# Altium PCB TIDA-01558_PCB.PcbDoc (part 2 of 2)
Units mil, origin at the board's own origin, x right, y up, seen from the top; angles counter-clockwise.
Board outline 2362.2 x 2362.2 mil, 2 copper layers (Top Layer, Bottom Layer), stack 64.8 mil thick; 83 components, 39 nets, 200 pads, 58 vias.
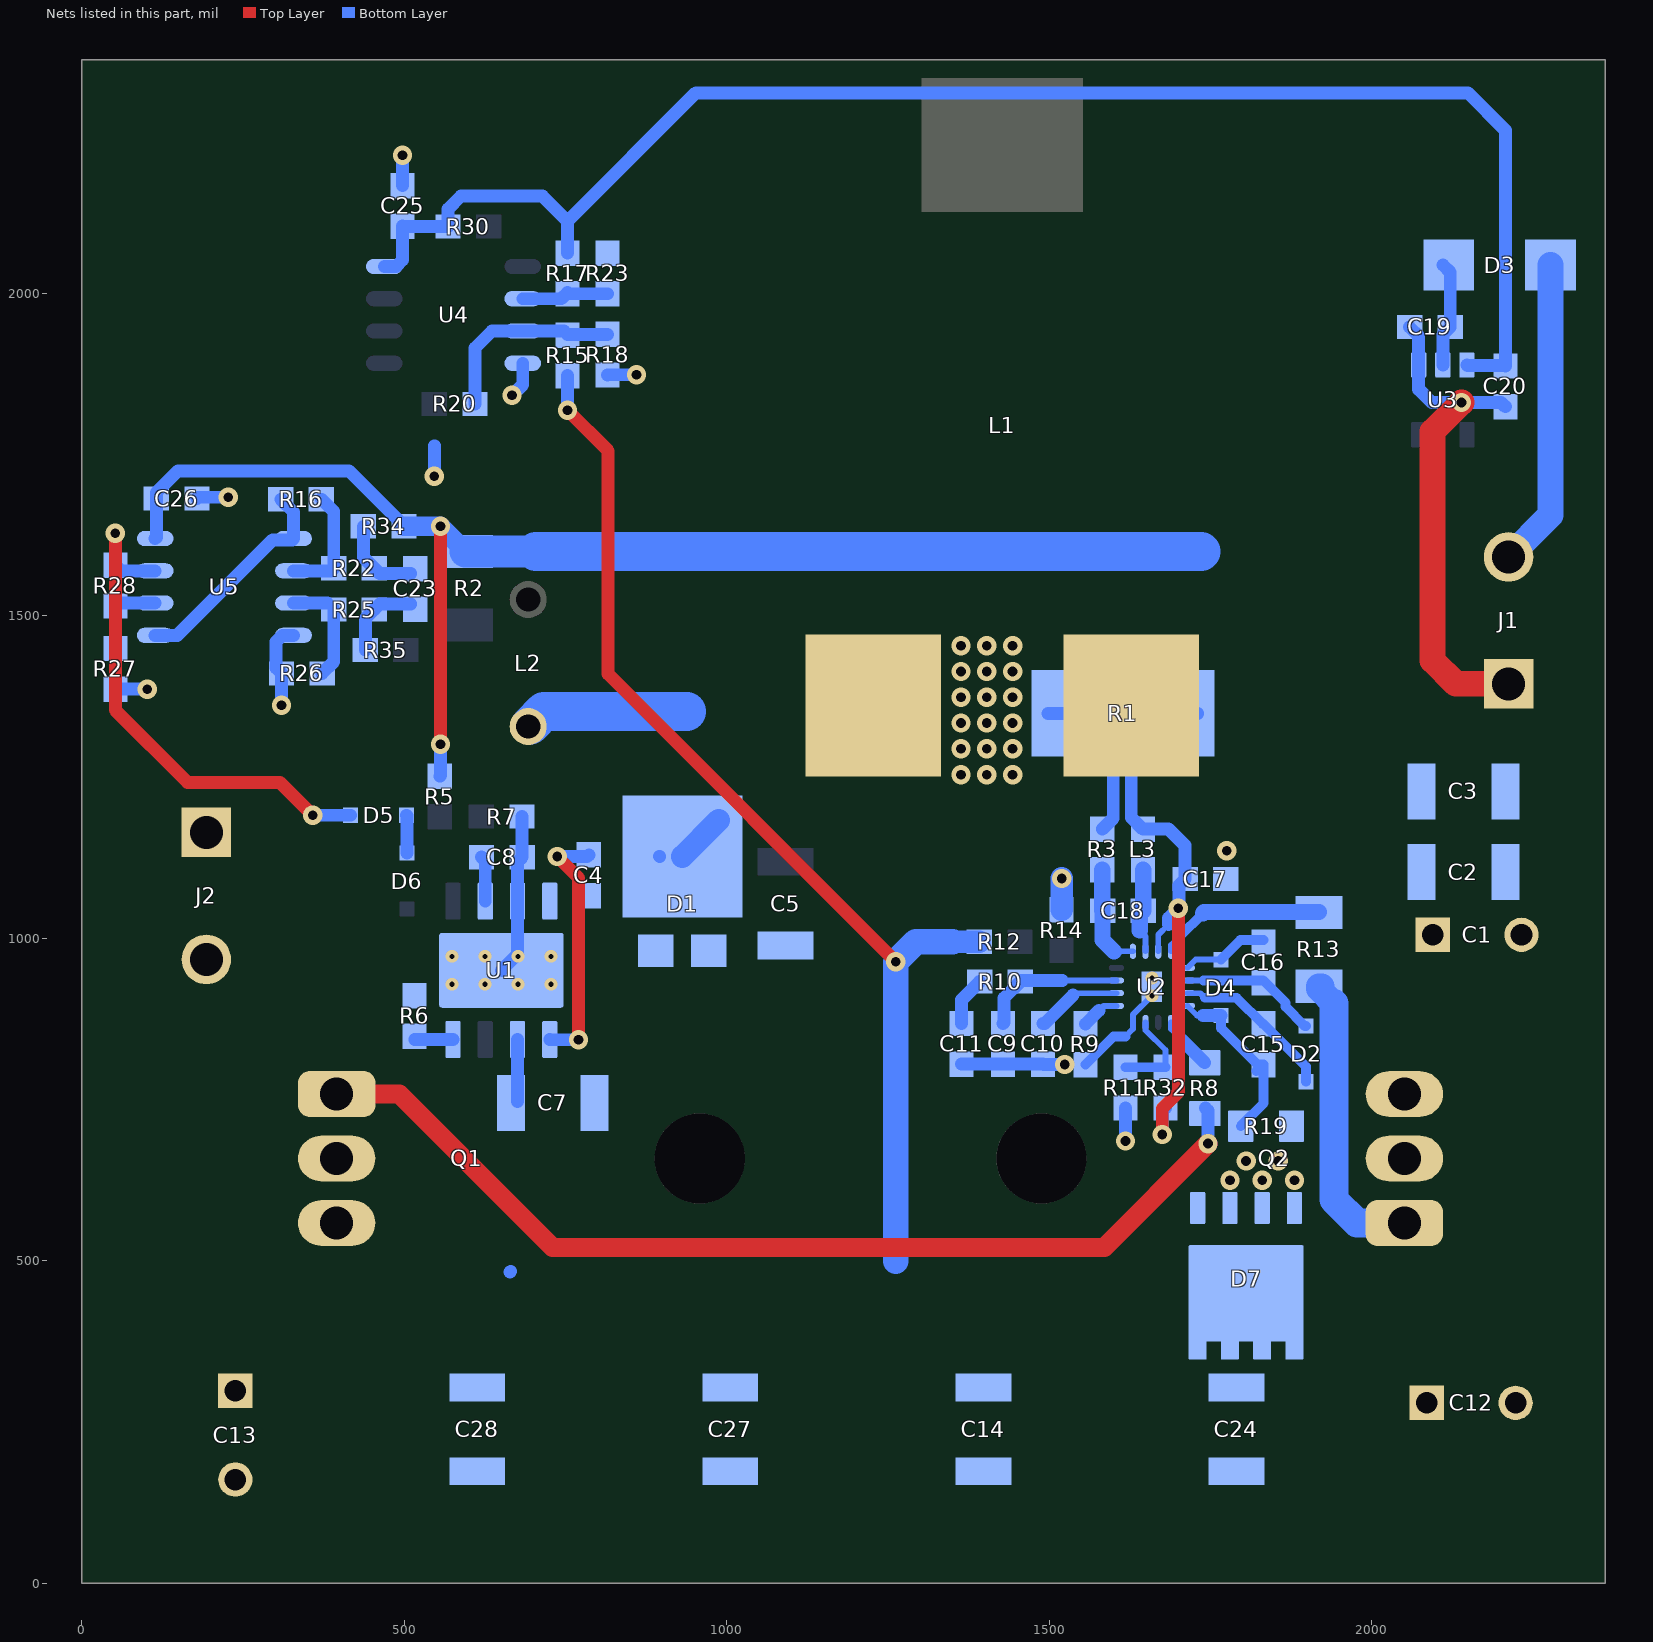
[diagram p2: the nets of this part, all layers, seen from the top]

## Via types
v1: diameter 30, hole 15, Top Layer to Bottom Layer, 48 vias
v2: diameter 19.68, hole 7.87, Top Layer to Bottom Layer, 10 vias

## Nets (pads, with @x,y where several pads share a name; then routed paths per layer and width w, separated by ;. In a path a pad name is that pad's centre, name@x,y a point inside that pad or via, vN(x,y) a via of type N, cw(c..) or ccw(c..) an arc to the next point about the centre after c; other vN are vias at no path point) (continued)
GND: C1.2 C2.2 C3.2 C5.2 C7.2 C8.2 C9.2 C10.2 C11.2 C12.2 C13.2 C14.2 C16.1 C17.2 C19.2 C20.2 C24.2 C25.2 C26.2 C27.2 C28.2 D1.1 D1.2 D4.2 J1.1 J2.1 Q2.3 R6.1 R7.1 R9.1 R11.1 R14.1 R18.1 R23.1 R26.1 R27.1 U1.7 U1.9@650.52,950.63 U2.9 U2.16 U2.17 U3.1 U4.4 U5.4 | length 2026.5
  Top Layer w40: v1(2139,1831) 2094,1786 2094,1431 2130,1395 J1.1@2203,1395
  Bottom Layer w9: 1618,848 1629.47,859.47 U2.16@1629.47,869.88 1629.47,881.69 v2(1659,911.22) ; U2.9@1714.12,954.53 1726.9,967.31 D4.2@1766,967.31
  Bottom Layer w15: R9.1@1556,804.5 1599.5,848 1618,848 ; D4.2@1766,967.31 1796.19,997.5 C16.1@1832,997.5
  Bottom Layer w20: R27.1@52,1386.5 v1(101.5,1386.5) ; C26.2@178.5,1682 180.5,1684 v1(227,1684) ; v1(309.5,1361.5) R26.1@309.5,1411 301,1419.5 301,1460 311,1470 U5.4@328.28,1470 ; C25.2@497.22,2167.27 v1(497.22,2214.22) ; v1(546.59,1716.41) 546.59,1763.82 ; U1.9@650.52,950.63 675.52,975.63 U1.7@675.52,1057.91 675.52,1118.83 C8.2@682.7,1126 R7.1@682.7,1188.8 ; v1(667,1842) 683.52,1858.52 U4.4@683.52,1891.86 ; R18.1@815,1873.5 815.5,1874 v1(860,1874) ; C11.2@1364,805.24 C9.2@1428,805.24 C10.2@1490,805.24 1490.73,804.5 v1(1524,804.5) ; v1(1618,686) R11.1@1618,737.24 ; C19.2@2058.5,1948 2072.6,1933.91 U3.1@2072.6,1889.13 2072.6,1851.4 2093,1831 v1(2139,1831) 2200.5,1831 C20.2@2207,1824.5
  Bottom Layer w35: R14.1@1519,1044.5 v1(1519,1093)
  other v1: 1775,1136
  other v2: 573.75,928.97 624.93,928.97 676.11,928.97 727.29,928.97 1659,938.78 573.75,972.28 624.93,972.28 676.11,972.28 727.29,972.28
ISNS+: C18.1 L3.1 U2.6 | length 132.6
  Bottom Layer w9: 1640.09,1012.09 1649.16,1003.01 U2.6@1649.16,980.12
  Bottom Layer w25: 1640.09,1012.09 1640.09,1037.59 C18.1@1645.5,1043 1645.5,1106.01 L3.1@1645,1106.5
ISNS-: C18.2 R3.1 U2.5 | length 163.5
  Bottom Layer w9: 1600,980 1600.12,980.12 U2.5@1629.47,980.12
  Bottom Layer w25: R3.1@1582,1106.5 1582,1043.5 C18.2@1582.5,1043 1582.5,997.5 1600,980
LDO_OP: C20.1 C25.1 R17.2 R30.1 U3.3 U4.8 | length 2428.1
  Bottom Layer w20: U4.8@468.95,2041.86 487.31,2041.86 497.22,2051.77 C25.1@497.22,2104.28 497.72,2103.77 R30.1@567.72,2103.77 567.72,2130.72 588,2151 714,2151 753,2112 ; R17.2@753,2062.5 753,2112 ; U3.3@2147.4,1889.13 2148.04,1888.5 2206,1888.5 C20.1@2207,1887.5 2207,2253 2149,2311 952,2311 753,2112
NetC4_1: C4.1 U1.1 | length 392.6
  Top Layer w20: v1(737,1127) 770,1094 v1(770,843)
  Bottom Layer w20: U1.1@725.68,843.5 U1.1@725.52,843.34 725.87,843 v1(770,843) ; v1(737,1127) 783.5,1127 C4.1@786,1129.5
NetC4_2: C4.2 D1.3 L2.1 U1.8 | length 332.3
  Bottom Layer w20: D1.3@895.43,1127.48 D1.3@895.93,1126.97
  Bottom Layer w35: D1.3@931,1127.11 D1.3@987.38,1183.5
  Bottom Layer w60: L2.1@695,1330.57 716.43,1352 938,1352
NetC8_1: C8.1 U1.6 | length 70.5
  Bottom Layer w20: C8.1@619.7,1126 625.52,1120.18 U1.6@625.52,1057.91
NetC9_1: C9.1 R10.2 U2.3 | length 225.6
  Bottom Layer w9: 1520,934.84 U2.3@1603.88,934.84
  Bottom Layer w20: C9.1@1428,868.23 1429.57,869.8 1429.57,907.57 R10.2@1455,933 1456.84,934.84 1520,934.84
NetC11_1: C11.1 R10.1 | length 76.4
  Bottom Layer w20: C11.1@1364,868.23 1364,904.99 R10.1@1392.01,933
NetC15_1: C15.1 D4.1 R19.1 U2.12 | length 290.4
  Bottom Layer w9: U2.12@1714.12,895.47 1728.9,880.69 1738.31,880.69
  Bottom Layer w15: D4.1@1766,880.69 D4.1@1766,880.39 1766,861 1822.5,804.5 1831,804.5 C15.1@1821,794.5 ; R19.1@1796.63,709 1831.93,744.3 C15.1@1831.93,804.5
  Bottom Layer w20: 1738.31,880.69 D4.1@1766,880.69
NetC15_2: C15.2 D2.1 U2.11 | length 253.8
  Bottom Layer w9: U2.11@1714.12,915.16 1714.31,914.97 1734,914.97 1740.97,908
  Bottom Layer w15: 1740.97,908 1790.5,908 C15.2@1831,867.5 ; C15.2@1831.93,867.5 1898,801.43 D2.1@1898,777.69
NetC16_2: C16.2 D2.2 U2.10 | length 216.8
  Bottom Layer w9: U2.10@1714.12,934.84 1739,934.84
  Bottom Layer w15: 1739,934.84 1831.66,934.84 1866.01,900.5 1866.01,894.15 1895.86,864.31 D2.2@1898,864.31
NetC19_1: C19.1 D3.2 U3.2 | length 164.3
  Bottom Layer w20: U3.2@2110,1889.13 2110,1936.5 C19.1@2121.5,1948 2121.5,2032.76 D3.2@2110.26,2044
NetC23_1: C23.1 R22.1 R34.2 | length 132
  Bottom Layer w20: R34.2@436.5,1639 436.5,1590.99 R22.1@453.5,1574 461.87,1565.62 C23.1@510,1565.62
NetC23_2: C23.2 R25.1 R35.2 | length 128.8
  Bottom Layer w20: R35.2@439.5,1447 439.5,1496.01 R25.1@453.5,1510 461.87,1518.38 C23.2@510,1518.38
NetD5_1: D5.1 R28.1 U5.7 | length 820.9
  Top Layer w20: v1(52,1628) 52,1354 164,1242 307,1242 v1(358,1191)
  Bottom Layer w20: v1(52,1628) R28.1@52,1578.5 60.5,1570 U5.7@113.72,1570 ; v1(358,1191) D5.1@416.69,1191
NetD5_2: D5.2 D6.2 | length 59
  Bottom Layer w20: D5.2@503.31,1191 504,1190.31 D6.2@504,1132.31
NetD7_1: D7.1 D7.2 D7.3 D7.4 L1.2 Q1.3 Q2.2@2050.39,658.89 R19.2 | length 68.7
  Top Layer w60: L1.2@1626.8,1360.84 L1.2@1626.8,1380.2
  Top Layer w80: L1.2@1626.8,1360.84 L1.2@1676.16,1360.84
  other v1: 1780,625 1830,625 1880,625 1805,655 1855,655
NetL1_1: L1.1 R1.2 R3.2 | length 269.5
  Bottom Layer w20: R1.2@1497.86,1349 1568,1349 1599,1318 1599,1186.5 R3.2@1582,1169.5
  other v1: 1363,1254 1403,1254 1443,1254 1363,1294 1403,1294 1443,1294 1363,1334 1403,1334 1443,1334 1363,1374 1403,1374 1443,1374 1363,1414 1403,1414 1443,1414 1363,1454 1403,1454 1443,1454
NetQ1_1: Q1.1 R8.2 | length 1572.9
  Top Layer w30: Q1.1@395.17,758.88 492.12,758.88 730,521 1585,521 v1(1746,682)
  Bottom Layer w20: R8.2@1742,737.24 1746,733.24 v1(1746,682)
NetQ2_1: Q2.1 R13.2 | length 492.8
  Bottom Layer w30: Q2.1@2033.51,542 Q2.1@2050.39,558.89
  Bottom Layer w40: R13.2@1922.09,925.91 R13.2@1918,925.91 1918,922 1941,899
  Bottom Layer w45: 1941,899 1941,595 1977.11,558.89 Q2.1@2050.39,558.89
NetR6_2: R6.2 U1.4 | length 59.4
  Bottom Layer w20: R6.2@516.2,843.5 516.36,843.34 U1.4@575.52,843.34
NetR8_1: R8.1 U2.13 | length 84.2
  Bottom Layer w9: U2.13@1688.53,869.88 1688.53,859.84 1705.37,843
  Bottom Layer w20: 1705.37,843 R8.1@1741,807.37
NetR9_2: R9.2 U2.1 | length 59.5
  Bottom Layer w9: 1576.75,888.25 1583.98,895.47 U2.1@1603.88,895.47
  Bottom Layer w20: R9.2@1556,867.5 1576.75,888.25
NetR11_2: R11.2 R32.2 U2.15 | length 144.4
  Bottom Layer w9: U2.15@1649.16,869.88 1649.16,857.84 1680,827 R32.2@1680,800.23
  Bottom Layer w15: R11.2@1618,800.23 R32.2@1680,800.23
NetR13_1: R13.1 U2.8 | length 260.3
  Bottom Layer w9: U2.8@1688.53,980.12 1688.53,989.64 1701.71,1002.83
  Bottom Layer w15: 1701.71,1002.83 1737.96,1039.07
  Bottom Layer w25: 1738,1039.07 1740.01,1041.09 R13.1@1918,1041.09
NetR15_1: R15.1 R18.2 R20.1 U4.3 | length 305.3
  Bottom Layer w20: R20.1@609.58,1828.82 609.58,1915.58 635.86,1941.86 U4.3@683.52,1941.86 747.59,1941.86 752.99,1936.46 R18.2@815,1936.5 R18.2@815,1936.5
NetR16_1: R16.1 R22.2 U5.2 | length 178.8
  Bottom Layer w20: U5.2@328.28,1570 386.5,1570 R22.2@390.5,1574 390.5,1661.99 R16.1@371.5,1681
NetR16_2: R16.2 U5.1 U5.5 | length 343.1
  Bottom Layer w20: U5.5@113.72,1470 148,1470 296,1618 U5.1@326.28,1618 ; R16.2@308.5,1681 328.28,1661.22 U5.1@328.28,1620
NetR17_1: R17.1 R23.2 U4.2 | length 135.5
  Bottom Layer w20: U4.2@683.52,1991.86 743.35,1991.86 R17.1@753,2001.5 ; R17.1@753,1999.5 R23.2@815.07,1999.5
NetR25_2: R25.2 R26.2 U5.3 | length 158.7
  Bottom Layer w20: U5.3@328.28,1520 R25.2@380.5,1520 ; R26.2@372.5,1411 390.5,1429.01 R25.2@390.5,1510
NetR27_2: R27.2 R28.2 U5.6 | length 129.6
  Bottom Layer w20: R27.2@52,1449.5 R28.2@52,1515.5 56.5,1520 U5.6@113.72,1520
SS: C10.1 U2.2 | length 134.1
  Bottom Layer w9: 1535.52,913.75 1536.93,915.16 U2.2@1603.88,915.16
  Bottom Layer w20: C10.1@1490,868.23 1492.81,868.23 1536.93,912.35
VBAT: C1.1 C2.1 C3.1 C17.1 C26.1 D3.1 J1.2 L3.2 R1.1 R2.2 R5.2 R32.1 R34.1 U2.7 U5.8 | length 3557.2
  Top Layer w20: v1(556,1301) v1(556,1639) ; v1(1675,696) 1675,736.54 1700,761.54 v1(1700,1047)
  Bottom Layer w9: U2.7@1668.84,980.12 1668.84,1005.84 1684.84,1021.84
  Bottom Layer w20: U5.8@113.72,1620 115.5,1621.79 C26.1@115.5,1682 115.5,1691.5 149,1725 414.17,1725 499.5,1639.67 R34.1@499.5,1639 ; R5.2@555,1251.5 556,1252.5 v1(556,1301) ; v1(1675,696) 1675,732.24 R32.1@1680,737.24 ; 1684.84,1021.84 1684.84,1031.84 v1(1700,1047) 1701,1048 1701,1082.5 C17.1@1710.5,1092 1710,1092.5 1710,1144.5 1685.01,1169.5 L3.2@1645,1169.5 1627,1187.5 1627,1315 1661,1349 R1.1@1730.14,1349
  Bottom Layer w30: R34.1@499.5,1639 v1(556,1639) R2.2@594.91,1600.09
  Bottom Layer w40: J1.2@2212,1591.43 2276.74,1656.17 D3.1@2276.74,2044
  Bottom Layer w50: R2.2@594.91,1600.09 R2.2@601,1600.09 704.09,1600.09
  Bottom Layer w60: 704.09,1600.09 1735.09,1600.09
VLINE: C7.1 C12.1 C13.1 C14.1 C24.1 C27.1 C28.1 D7.5 D7.6 D7.7 D7.8 D7.9 J2.2 Q1.2@395.17,658.88 R12.2 R15.2 U1.2 | length 1823
  Top Layer w20: v1(753,1819) 816,1756 816,1410 v1(1262,964)
  Bottom Layer w20: 664,483 665.04,484.04 ; C7.1@675.52,747.52 U1.2@675.52,843.34 ; v1(753,1819) R15.2@753,1872.5
  Bottom Layer w35: 1350,995 R12.2@1391.5,995
  Bottom Layer w40: 1262,500 v1(1262,964) 1293,995 1350,995
pads on no net: H13. L1.3 Q1.2@798.02,658.88 Q2.2@1647.55,658.89 U1.9@650.52,950.63 U2.14 U3.4 U3.5 U4.5 U4.6 U4.7

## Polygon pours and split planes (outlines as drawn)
GND on Bottom Layer "GND_L02_P043" (solid, remove dead copper, pour order 43): 0,1388 52,1336 482,1336 538,1392 538,1503 876,1841 876,2268 781,2363 34,2363 0,2329
GND on Bottom Layer "GND_L02_P041" (solid, remove dead copper, pour order 41): 42,1296 209,1296 496,1009 622,1009 622,883 472,883 309,1046 174,1046 137,1009 137,313.37 220.37,230 2126,230 2144,248 2144,310 1974,480 1974,932 1994,952 2124,952 2137,965 2137,1425 2192,1480 2303,1480 2362.2,1420.8 2362.2,53.2 2309,0 70,0 2,68 2,1256
VBAT on Bottom Layer "VBAT_L02_P008" (solid, remove dead copper, pour order 8): 1700,1404 1700,1274 1754,1220 1825,1220 2072,973 2117,973 2122,978 2122,1447 2253,1578 2253,1635 2201,1687 1761,1687 1701.23,1627.23
NetL1_1 on Bottom Layer "NETL1_1_L02_P010" (solid, remove dead copper, pour order 10): 1502,1484 1526,1460 1526,1268 1497,1239 1175,1239 1150,1264 1150,1453 1181,1484
GND on Bottom Layer "GND_L02_P012" (solid, remove dead copper, pour order 12): 1136,1012 1146,1002 1146,855 980.88,689.88 784.12,689.88 762,712 762,879 753,888 496,888 488,896 488,1005 495,1012
NetC4_2 on Bottom Layer "NETC4_2_L02_P014" (solid, remove dead copper, pour order 14): 1023.61,1027.5 1025.49,1029.38 1025.49,1383 828,1383 828,1107 811,1090 715,1090 710,1085 710,1034 716.5,1027.5
VLINE on Bottom Layer "VLINE_L02_P049" (solid, remove dead copper, pour order 49): 153,998 153,319 226,246 2106,246 2114,254 2114,309 1885,538 902,538 612,828 504,828 316,1016 171,1016
NetD7_1 on Bottom Layer "Bottom Layer-No Net" (solid, remove dead copper, pour order 55): 1852,685 1841,674 1781,674 1716,609 1716,560 1720,556 1894.92,556 1900,561.08 1900,733 1896,737 1855,737 1852,734
GND on Bottom Layer "GND_L02_P057" (solid, remove dead copper, pour order 57): 1292,762 1435,619 1828,619 2083,874 2083,940 1818,1205 1342,1205 1292,1155
GND on Top Layer "NET" (solid, remove dead copper, pour order 53): 1291,1150 1291,743.74 1352.74,682 1382.74,652 1724,652 1746,652 1792,698 1792,1165 1752,1205 1343,1205 1292,1154
GND on Top Layer "GND_L01_P045" (solid, remove dead copper, pour order 45): 4,2270 4,85 68.61,20.39 2313.39,20.39 2355,62 2355,1426 2323,1458 2073,1458 1988,1373 1988,564 1652,228 418,228 299,347 299,831 335,867 411,867 497,867 612,752 632,732 819,732 839,752 839,1188 812,1215 659,1215 594,1280 594,1558 875.82,1839.82 875.82,2266.18 784,2358 87,2358 1,2272
NetD7_1 on Top Layer "NETD7_1_L01_P027" (solid, remove dead copper, pour order 27): 332,575 332,350 437,245 1627,245 2003,621 2093,621 2113,641 2113,677 2093,697 2011.74,697 1971,737.74 1971,914 1971,1363 1860,1474 1523,1474 1518,1469 1518,1253 1525,1246 1751,1246 1812,1185 1812,698 1615,501 632,501 535,598 355,598
NetL1_1 on Top Layer "NETL1_1_L01_P015" (solid, remove dead copper, pour order 15): 1111,1467 1111,1258 1137,1232 1450,1232 1466,1248 1466,1458 1442,1482 1126,1482

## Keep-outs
Keep-Out Layer:
  the board outline again, w10

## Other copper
Top Layer:
  text ".Layer_Name" at 271,-1248.49 h60
Bottom Layer:
  text ".Layer_Name" at 271,-1248.49 h60

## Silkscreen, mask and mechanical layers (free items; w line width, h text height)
Top Overlay:
  lines w10: 2266,1296 2266,1287 ; 2303,1286 2303,1278 2266,1278 2266,1287 ; 2304,1296 2303,1295 2303,1287 2266,1287
  text "TIDA-01558-E1" at 44,2001 h120
  text "20-28V,20A" at 2047,1777 h30
  text "VBAT" at 2141,1712 h40
  text "GND" at 145,1282 h40
  text "GND" at 2129,1238 h40
  text "VLINE" at 29,815 h40
  text "30-38V,20A" at 65,499 h30 r90
  text ".Layer_Name" at 271,-1248.49 h60
Bottom Overlay:
  lines w6: 419,1410 419,1401 424,1396 624,1396 657,1429 657,1654 622,1689 427,1689 419,1681 419,1675 ; 869,1791 869,1801 874,1806 968,1806 1008,1766 1008,1617 976,1585 878,1585 870,1593 870,1598 ; 1353,758 1392,758 1400,766 ; 1439,741 1457,741 1481,765 ; 1540,1113 1540,1087 1546,1081 ; 1587,685 1587,692 1590,695 ; 1647,680 1647,692 1652,697 ; 1716,685 1716,693 1720,697 ; 1942,873 1986,873 1993,866
  text ".Layer_Name" at 271,-1248.49 h60
Top Paste:
  text ".Layer_Name" at 271,-1248.49 h60
Bottom Paste:
  text ".Layer_Name" at 271,-1248.49 h60
Top Solder:
  text ".Layer_Name" at 271,-1248.49 h60
  text ".Layer_Name" at 271,-1248.49 h60
Bottom Solder:
  text ".Layer_Name" at 271,-1248.49 h60
Drill Guide:
  text ".Layer_Name" at 271,-1248.49 h60
M1 Board Outline:
  the board outline again, w10
M2 Board Dimensions:
  rectangle: -306,-665 -181,-540
  rectangle: -181,-790 194,-665
  lines w7: -306,-665 694,-665 ; -181,-790 -181,-540 ; -56,-790 -56,-540 ; 194,-790 194,-540 ; 444,-790 444,-540 ; -306,-790 694,-790 694,-540 -306,-540 -306,-790
M3 3D STEP Top:
  text ".Layer_Name" at 271,-1248.49 h60
M4 3D STEP Bottom:
  text ".Layer_Name" at 271,-1248.49 h60
M5 Assembly Top:
  lines w10: -598,-1320.17 6002,-1320.17 ; -598,-1116.83 6004,-1116.83 ; -598,-913.5 -598,-1523.5 3407,-1523.5 6004,-1523.5 6004,-913.5 -597.5,-913.5 -597.5,-1523.5 978,-1523.5 ; 1867,-1523.5 1867,-913.5 ; 3134,-1116.83 3134,-913.5 ; 3974,-1116.83 3974,-913.5 ; 4596,-1530 4596,-1327.17
  text "COMPONENTS MARKED 'DNP' SHOULD NOT BE POPULATED." at 847.5,-708.5 h60
  text "ASSEMBLY VARIANT:" at 847,-824 h60
  text ".VariantName" at 1883,-824 h60
  text "PCB VIEWED FROM TOP SIDE" at -534.5,-1045.67 h60
  text "BOARD #:" at 1942,-1045.67 h60
  text ".PRJ_Number" at 2487.5,-1045.67 h60
  text "REV:" at 3332,-1045.67 h60
  text ".PCB_Rev" at 3623.5,-1045.67 h60
  text "SVN REV:" at 4170,-1045.67 h60
  text ".VersionControl_RevNumber" at 4676,-1045.67 h60
  text "LAYER NAME =" at -534.5,-1248.49 h60
  text "'.Layer_Name'" at 271,-1248.49 h60
  text "TID #:" at 1942,-1249 h60
  text ".TID" at 2487.5,-1249 h60
  text "PLOT NAME =" at -534.5,-1454.34 h60
  text ".plot_File_Name" at 271,-1454.34 h60
  text "GENERATED    :" at 1944,-1454.34 h60
  text ".Print_Date" at 2813.5,-1454.34 h60
  text ".Print_Time" at 3542.5,-1454.34 h60
  text "TEXAS INSTRUMENTS" at 4807,-1454.34 h60
M6 Assembly Bottom:
  circle w10: c2048.98,1881 r1
  lines w10: -598.5,-1117.33 6003.5,-1117.33 ; -596.5,-1320.67 6003.5,-1320.67 ; 809.5,-1530.5 809.5,-1327.67 ; 1431.5,-1117.33 1431.5,-914 ; 2271.5,-1117.33 2271.5,-914 ; 3538.5,-1524 3538.5,-914 ; 4427.5,-1524 6003,-1524 6003,-914 -598.5,-914 -598.5,-1524 1998.5,-1524 6003.5,-1524 6003.5,-914
  text "COMPONENTS MARKED 'DNP' SHOULD NOT BE POPULATED." at 5796,-708 h60
  text ".VariantName" at 4752,-824 h60
  text "ASSEMBLY VARIANT:" at 5791,-824 h60
  text ".VersionControl_RevNumber" at 729.5,-1046.17 h60
  text "SVN REV:" at 1235.5,-1046.17 h60
  text ".PCB_Rev" at 1782,-1046.17 h60
  text "REV:" at 2073.5,-1046.17 h60
  text ".PRJ_Number" at 2918,-1046.17 h60
  text "BOARD #:" at 3463.5,-1046.17 h60
  text "PCB VIEWED FROM BOTTOM SIDE" at 5940,-1046.17 h60
  text "LAYER NAME =" at 5937,-1243 h60
  text "'.Layer_Name'" at 5184,-1244 h60
  text ".TID" at 2918,-1249.5 h60
  text "TID #:" at 3463.5,-1249.5 h60
  text "TEXAS INSTRUMENTS" at 598.5,-1454.84 h60
  text ".Print_Time" at 1863,-1454.84 h60
  text ".Print_Date" at 2592,-1454.84 h60
  text "GENERATED    :" at 3461.5,-1454.84 h60
  text ".plot_File_Name" at 5134.5,-1454.84 h60
  text "PLOT NAME =" at 5940,-1454.84 h60
M9 Title Sheet:
  drawing of 57 lines, arcs and shapes, not listed
  text "1" at 433.84,7646.5 h70
  text "2" at 2929.5,7646.5 h70
  text "3" at 5418.84,7646.5 h70
  text "4" at 7925.51,7646.5 h70
  text "5" at 10424.5,7646.5 h70
  text "6" at 12929.5,7646.5 h70
  text "A" at -722.5,6503.5 h70
  text "A" at 14077.5,6503.5 h70
  text "B" at -722.5,4123.5 h70
  text "B" at 14077.5,4123.5 h70
  text "C" at -722.5,1748.5 h70
  text "C" at 14077.5,1748.5 h70
  text "PROJECT TITLE:" at 11037.5,-112.5 h45
  text ".PRJ_Title" at 11087.5,-245.83 h70
  text "DESIGNED FOR:" at 11037.5,-413.5 h45
  text ".PRJ_Customer" at 11087.5,-553.5 h70
  text "D" at -722.5,-621.5 h70
  text "D" at 14077.5,-621.5 h70
  text "FILE NAME:" at 11037.5,-713.5 h45
  text ".PCB_File_Name_No_Path" at 11087.5,-833.5 h70
  text "Texas Instruments (TI) and/or its licensors do not warrant the accuracy or completeness of this specification" at 6068,-995.34 h45
  text "ENGINEER:" at 11037.5,-1003.5 h45
  text "LAYOUT BY:" at 12542.5,-1003.5 h45
  text "or any information contained therein. TI and/or its licensors do not warrant that this design will meet" at 6023.01,-1108 h45
  text ".PRJ_Engineer" at 11087.5,-1158.49 h70
  text ".PCB_Layout" at 12593,-1158.49 h70
  text "the specifications, will be suitable for your application or fit for any particular purpose, or will operate in" at 6023.01,-1220.67 h45
  text "ALTIUM DESIGNER VERSION:" at 12542.5,-1313.5 h45
  text "an implementation. TI and/or its licensors do not warrant that the design is production worthy. You should" at 6023.01,-1333.33 h45
  text "completely validate and test your design implementation to confirm the system functionality for your application." at 6068,-1446 h45
  text ".print_Scale" at 11087.5,-1446.83 h70
  text ".Application_BuildNumber" at 12593,-1446.83 h70
  text "1" at 433.84,-1653.5 h70
  text "2" at 2929.5,-1653.5 h70
  text "3" at 5418.84,-1653.5 h70
  text "4" at 7925.51,-1653.5 h70
  text "5" at 10424.5,-1653.5 h70
  text "6" at 12929.5,-1653.5 h70
M10 Fab Notes:
  drawing of 173 lines, arcs and shapes, not listed
  text "DESIGN INFORMATION" at 12071.02,5811 h60
  text "MIN. TRACK WIDTH:" at 11426.46,5631 h60
  text "9" at 12522.7,5631 h60
  text "MIL" at 12677.46,5631 h60
  text "MIN. CLEARANCE:" at 11426.46,5499 h60
  text "0.2" at 12462.7,5499 h60
  text "mm" at 12677.46,5499 h60
  text "19.68" at 12374,5370 h60
  text "MIN. VIA PAD SIZE:" at 11426.46,5367 h60
  text "MIL" at 12677.46,5367 h60
  text "0.05mm (2MIL)" at 12121.46,5225.29 h60
  text "MINIMUM ANNULAR RING" at 11097.23,5221 h60
  text "EXTERNAL" at 12829.46,5221 h60
  text "PER" at 11297.23,5103 h60
  text "IPC-D-275 CLASS 2 LEVEL C" at 11517.23,5103 h60
  text "MIL, HOLES" at 13005.46,4990.71 h60
  text "+/-" at 12613,4990 h60
  text "+/-" at 13467,4990 h60
  text "REGISTRATION TOLERANCES:" at 11097.23,4985 h60
  text "METAL" at 12297,4985 h60
  text "5" at 12873.2,4985 h60
  text "3" at 13706.2,4985 h60
  text "MIL" at 13822.46,4985 h60
  text "+/-" at 13467,4872 h60
  text "HOLE SIZE TOLERANCE (UNLESS OTHERWISE SPECIFIED):" at 11097.23,4867 h60
  text "3" at 13706.2,4867 h60
  text "MIL" at 13822.46,4867 h60
  text "MATERIAL:" at 11022.46,4657.54 h60
  text "FR-4 High Tg" at 12008.9,4517.21 h60
  text "FR-408" at 11443.46,4508.64 h60
  text "OTHER" at 12931.46,4508.64 h60
  text "X" at 11854,4505 h60
  text "62 MIL (1.6mm) +/-10%" at 11763.56,4345.92 h60
  text "THICKNESS:" at 11097.23,4341.64 h60
  text "X" at 11635.4,4341.64 h60
  text "OTHER" at 13048.46,4341.64 h60
  text "TOLERANCE:" at 11097.23,4183.64 h60
  text "X" at 11936.53,4183.64 h60
  text "ANSI IPC-6012 TYPE 3 CLASS 2" at 12123.48,4183.64 h60
  text "OTHER +/-" at 12123.46,4027.64 h60
  text "BOW & TWIST:" at 11097.23,3870.64 h60
  text "X" at 11936.53,3870.64 h60
  text "ANSI IPC-6012 TYPE 3 CLASS 2" at 12123.48,3870.64 h60
  text "OTHER +/-" at 12123.46,3712.13 h60
  text "DRILLING:" at 11022.46,3573.64 h60
  text "REFERENCE:" at 11097.23,3456.64 h60
  text "X" at 11745.46,3456.64 h60
  text "AS SHOWN" at 11932.46,3456.64 h60
  text "X" at 12646.46,3456.64 h60
  text "NC_DRILL FILES" at 12783.46,3456.64 h60
  text "PTH COPPER THICKNESS:" at 11097.23,3298.64 h60
  text "X" at 12227.46,3298.64 h60
  text "20-30 um" at 12364.46,3298.64 h60
  text "OTHER" at 13081.46,3298.64 h60
  text "BOARD FINISH:" at 11022.46,3139.64 h60
  text "SILKSCREEN:" at 11177.68,3021.64 h60
  text "X" at 12126.46,3021.64 h60
  text "TOP" at 12252.46,3021.64 h60
  text "X" at 12636.46,3021.64 h60
  text "BOTTOM" at 12763.46,3021.64 h60
  text "SILKSCREEN COLOR:" at 11177.68,2854.64 h60
  text "X" at 12125.42,2854.64 h60
  text "WHITE" at 12252.46,2854.64 h60
  text "OTHER" at 12763.46,2854.64 h60
  text "X" at 12256.42,2695.44 h60
  text "GREEN" at 12383.46,2695.44 h60
  text "OTHER" at 13001.46,2695.44 h60
  text "SOLDER RESIST COLOR:" at 11177.68,2684.64 h60
  text "X" at 12256.42,2525.44 h60
  text "MATTE" at 12383.46,2525.44 h60
  text "SEMI-GLOSS" at 13001,2524.8 h60
  text "IMMERSION GOLD (ENIG)" at 12083.46,2336.92 h60
  text "ENEPIG" at 13421,2333.64 h60
  text "SURFACE FINISH:" at 11022.46,2332.64 h60
  text "X" at 11896.51,2332.64 h60
  text "IMM. TIN/SILVER OR EQUIV" at 11352,2175.64 h60
  text "OTHER" at 12783.46,2175.64 h60
  text "ARRAY/PANEL:" at 11022.46,1996.64 h60
  text "CUT AND TRIM PER M1 BOARD OUTLINE" at 12083.46,1992.35 h60
  text "N.C. ROUTE" at 12083.46,1840.64 h60
  text "X" at 12762.46,1840.64 h60
  text "V. SCORE" at 12949.46,1840.64 h60
  text "CERTIFICATION:" at 11022.46,1703.64 h60
  text "MATERIALS AND WORKMANSHIP FOR ALL PCBS" at 11747.46,1703.64 h60
  text "TO MEET OR EXCEED THE REQUIREMENTS OF:" at 11747.46,1605.64 h60
  text "X" at 11373.96,1469.13 h60
  text "ANSI IPC-A-600F CLASS ->" at 11512.96,1469.13 h60
  text "X" at 13152.02,1469.13 h60
  text "2" at 13270.96,1469.14 h60
  text "1" at 12955.96,1467.64 h60
  text "3" at 13624.96,1467.64 h60
  text "X" at 12188.02,1309.64 h60
  text "RoHS" at 12324.96,1309.64 h60
  text "OTHER" at 12969.36,1309.64 h60
  text "PER ORDER" at 13366.42,1309.64 h60
  text "ALL BOARDS MUST MEET OR EXCEED UL94-V0 REQUIREMENTS." at 11050,1144 h60
  text "PCB MUST BEAR THE UL94V-0 UL REGISTERED MATERIAL ID NUMBER" at 11050,1024 h60
  text "ADDITIONAL REQUIREMENTS:" at 11022.46,850.64 h60
  text "MICROSECTION:" at 11097.23,735.64 h60
  text "YES" at 12002.96,735.64 h60
  text "REQUIRED" at 12864.46,579.49 h60
  text "BARE BOARD ELEC. TEST:" at 11097.23,576.64 h60
  text "NONE" at 12402.96,576.64 h60
  text "X" at 12737.46,576.64 h60
  text "PER ORDER" at 13456.46,576.64 h60
  text "THIS IS NOT AN IMPEDANCE CONTROL BOARD" at 3760,22 h60
  text "COPPER THICKNESS IS 2oz" at 3760,-97 h60
M11 Gerber Information:
  lines w10: -598,-1320.17 6002,-1320.17 ; -598,-1116.83 6004,-1116.83 ; -598,-913.5 -598,-1523.5 3407,-1523.5 6004,-1523.5 6004,-913.5 -597.5,-913.5 -597.5,-1523.5 978,-1523.5 ; 1867,-1523.5 1867,-913.5 ; 3134,-1116.83 3134,-913.5 ; 3974,-1116.83 3974,-913.5 ; 4596,-1530 4596,-1327.17
  text "ALL ARTWORK VIEWED FROM TOP SIDE" at -534.5,-1045.67 h60
  text "BOARD #:" at 1942,-1045.67 h60
  text ".PRJ_Number" at 2487.5,-1045.67 h60
  text "REV:" at 3332,-1045.67 h60
  text ".PCB_Rev" at 3623.5,-1045.67 h60
  text "SVN REV:" at 4170,-1045.67 h60
  text ".VersionControl_RevNumber" at 4676,-1045.67 h60
  text "LAYER NAME =" at -534.5,-1248.49 h60
  text "TID #:" at 1942,-1249 h60
  text ".TID" at 2487.5,-1249 h60
  text "PLOT NAME =" at -534.5,-1454.34 h60
  text ".plot_File_Name" at 271,-1454.34 h60
  text "GENERATED    :" at 1944,-1454.34 h60
  text ".Print_Date" at 2813.5,-1454.34 h60
  text ".Print_Time" at 3542.5,-1454.34 h60
  text "TEXAS INSTRUMENTS" at 4807,-1454.34 h60
M12 Stackup:
  drawing of 191 lines, arcs and shapes, not listed
  text "Layer" at 9492.08,7440 h60
  text "Name" at 9901.99,7440 h60
  text "Material" at 10831.73,7440 h60
  text "Thickness" at 11691.5,7440 h60
  text "Constant" at 12341.34,7440 h60
  text "Board Layer Stack" at 12911.2,7440 h60
  text "1" at 9492.08,7320 h60
  text "Top Overlay" at 9901.99,7320 h60
  text "2" at 9492.08,7200 h60
  text "Top Solder" at 9901.99,7200 h60
  text "Solder Resist" at 10831.73,7200 h60
  text "0.40mil" at 11691.5,7200 h60
  text "3.5" at 12341.34,7200 h60
  text "3" at 9492.08,7080 h60
  text "Top Layer" at 9901.99,7080 h60
  text "Copper" at 10831.73,7080 h60
  text "2.80mil" at 11691.5,7080 h60
  text "4" at 9492.08,6960 h60
  text "Dielectric1" at 9901.99,6960 h60
  text "FR-4 High Tg" at 10831.73,6960 h60
  text "59.20mil" at 11691.5,6960 h60
  text "4.8" at 12341.34,6960 h60
  text "5" at 9492.08,6840 h60
  text "Bottom Layer" at 9901.99,6840 h60
  text "Copper" at 10831.73,6840 h60
  text "2.80mil" at 11691.5,6840 h60
  text "6" at 9492.08,6720 h60
  text "Bottom Solder" at 9901.99,6720 h60
  text "Solder Resist" at 10831.73,6720 h60
  text "0.40mil" at 11691.5,6720 h60
  text "3.5" at 12341.34,6720 h60
  text "7" at 9492.08,6600 h60
  text "Bottom Overlay" at 9901.99,6600 h60
M13 Component Bodies Top:
  text ".Layer_Name" at 271,-1248.49 h60
M14 Component Bodies Bottom:
  text ".Layer_Name" at 271,-1248.49 h60
M15 Courtyards Top:
  text ".Layer_Name" at 271,-1248.49 h60
M16 Courtyards Bottom:
  text ".Layer_Name" at 271,-1248.49 h60
Drill Drawing:
  circle w10: c3339.71,2788.15 r27.69
  circle w10: c3339.71,2788.15 r46.14
  circle w10: c3339.71,2165.22 r46.14
  lines w10: 3293.57,1726.86 3316.64,1726.86 3339.71,1703.79 3362.78,1726.86 3385.85,1726.86 3362.78,1749.93 3385.85,1773 3362.78,1773 3339.71,1796.07 3316.64,1773 3293.57,1773 3316.64,1749.93 3293.57,1726.86 ; 3293.57,2003.72 3385.85,2003.72 3339.71,1911.43 3293.57,2003.72 ; 3293.57,2326.72 3385.85,2326.72 3385.85,2419 3293.57,2419 3293.57,2326.72 ; 3293.57,2557.43 3316.64,2557.43 3339.71,2534.36 3362.78,2557.43 3385.85,2557.43 3362.78,2580.5 3385.85,2603.58 3362.78,2603.58 3339.71,2626.65 3316.64,2603.58 3293.57,2603.58 3316.64,2580.5 3293.57,2557.43 ; 3312.03,2566.66 3325.87,2566.66 3339.71,2552.82 3353.55,2566.66 3367.4,2566.66 3353.55,2580.5 3367.4,2594.35 3353.55,2594.35 3339.71,2608.19 3325.87,2594.35 3312.03,2594.35 3325.87,2580.5 3312.03,2566.66
  lines w12: 3212,1641.49 6510.31,1641.49 ; 3212,2887.36 6510.31,2887.36 ; 3775.59,1433.85 3775.59,3095 ; 4329,1433.85 4329,3095 ; 5390.27,1433.85 5390.27,3095 ; 5822.47,1433.85 5822.47,3095 ; 3212,1433.85 6510.31,1433.85 6510.31,3095 3212,3095 3212,1433.85
  text "Symbol" at 3336.59,2949.65 h120
  text "Quantity" at 3837.88,2949.65 h120
  text "Finished Hole Size" at 4391.29,2949.65 h120
  text "Plated" at 5452.56,2949.65 h120
  text "Hole Type" at 5884.77,2949.65 h120
  text "2" at 3837.88,2742.01 h100
  text "140.00mil (3.556mm)" at 4391.29,2742.01 h100
  text "NPTH" at 5452.56,2742.01 h100
  text "Round" at 5884.77,2742.01 h100
  text "10" at 3837.88,2534.36 h100
  text "7.87mil (0.200mm)" at 4391.29,2534.36 h100
  text "PTH" at 5452.56,2534.36 h100
  text "Round" at 5884.77,2534.36 h100
  text "48" at 3837.88,2326.72 h100
  text "15.00mil (0.381mm)" at 4391.29,2326.72 h100
  text "PTH" at 5452.56,2326.72 h100
  text "Round" at 5884.77,2326.72 h100
  text "6" at 3837.88,2119.07 h100
  text "33.47mil (0.850mm)" at 4391.29,2119.07 h100
  text "PTH" at 5452.56,2119.07 h100
  text "Round" at 5884.77,2119.07 h100
  text "2" at 3837.88,1911.43 h100
  text "37.56mil (0.954mm)" at 4391.29,1911.43 h100
  text "PTH" at 5452.56,1911.43 h100
  text "Round" at 5884.77,1911.43 h100
  text "10" at 3837.88,1703.79 h100
  text "51.18mil (1.300mm)" at 4391.29,1703.79 h100
  text "PTH" at 5452.56,1703.79 h100
  text "Round" at 5884.77,1703.79 h100
  text "78 Total" at 3837.88,1496.14 h100
  text "DRILL TABLE" at 3768,594 h60
  text "FOR PTH +3/-3MIL" at 3764,469 h60
  text "FOR NPTH +2/-2MIL" at 3764,360 h60
  text "FOR 7.87MIL PTH +0/-7.87MIL" at 3764,248 h60
  text "FOR 15MIL PTH +0/-15MIL" at 3764,134 h60
  text ".Layer_Name" at 271,-1248.49 h60

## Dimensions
0,0 to 0,2362.2 on M2 Board Dimensions
0,0 to 2362.2,0 on M2 Board Dimensions
-306,-790 to 694,-790 on M2 Board Dimensions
